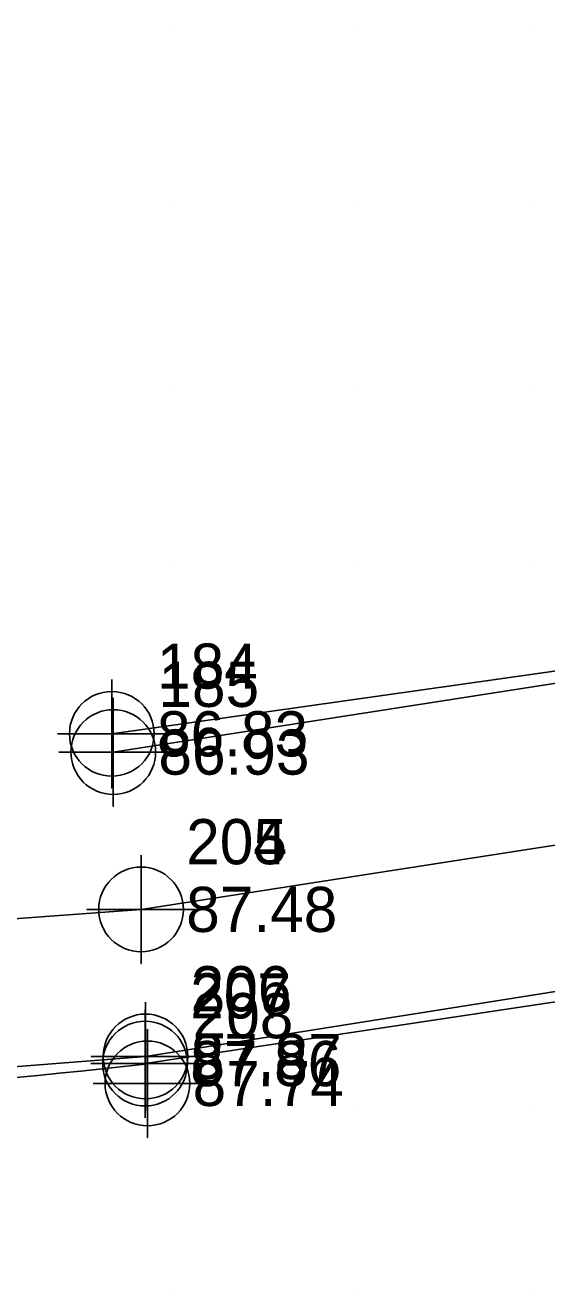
# Model space of a CAD drawing. Extents: x 1988140 to 1988766, y 249950 to 250250.
# Drawn here: x 1988371.8 to 1988400.7, y 250030 to 250100 of the extents above; entities that cross this region are included whole.
import ezdxf

# ---------------------------------------------------------------- set-up
doc = ezdxf.new("R2010")
doc.units = 0
for name, color, linetype in [('Exist DTM Crownline', 7, 'Continuous'), ('Exist DTM Crownline Cogo Elevation', 7, 'Continuous'), ('Exist DTM Crownline Cogo Number', 7, 'Continuous'), ('Exist DTM Crownline Cogo Point CELL', 7, 'Continuous'), ('Exist DTM QL2 LIDAR Elevation Point', 7, 'Continuous'), ('Exist DTM Regular Point CELL', 7, 'Continuous'), ('Exist DTM Regular Point Cogo Elevation', 7, 'Continuous'), ('Exist DTM Regular Point Cogo Number', 7, 'Continuous'), ('Exist Roads EOP', 7, 'Continuous'), ('Exist Roads EOP Cogo Elevation', 7, 'Continuous'), ('Exist Roads EOP Cogo Number', 7, 'Continuous'), ('Exist Roads EOP Cogo Point CELL', 7, 'Continuous'), ('Exist Roads EOT', 7, 'Continuous'), ('Exist Roads EOT Cogo Elevation', 7, 'Continuous'), ('Exist Roads EOT Cogo Number', 7, 'Continuous'), ('Exist Roads EOT Cogo Point CELL', 7, 'Continuous')]:
    doc.layers.add(name, color=color, linetype=linetype)

msp = doc.modelspace()

# ---------------------------------------------------------------- linework, layer by layer
at = {"layer": 'Exist DTM Crownline'}
msp.add_lwpolyline([(1988342.6848, 250048.4444), (1988378.1968, 250051.0543), (1988417.6158, 250057.1729)], dxfattribs=at)
at = {"layer": 'Exist DTM Crownline Cogo Point CELL'}
msp.add_lwpolyline([(1988378.1968, 250054.0543), (1988378.1968, 250048.0543), (1988378.1968, 250051.0543), (1988381.1968, 250051.0543), (1988375.1968, 250051.0543)], dxfattribs=at)
msp.add_circle((1988378.1968, 250051.0543), 2.344, dxfattribs=at)
at = {"layer": 'Exist DTM QL2 LIDAR Elevation Point'}
for p, q in [((1988380, 250100), (1988380, 250100)), ((1988390, 250100), (1988390, 250100)), ((1988400, 250100), (1988400, 250100)), ((1988380, 250090), (1988380, 250090)), ((1988390, 250090), (1988390, 250090)), ((1988400, 250090), (1988400, 250090)), ((1988380, 250080), (1988380, 250080)), ((1988390, 250080), (1988390, 250080)), ((1988400, 250080), (1988400, 250080)), ((1988380, 250070), (1988380, 250070)), ((1988390, 250070), (1988390, 250070)), ((1988400, 250070), (1988400, 250070)), ((1988380, 250040), (1988380, 250040)), ((1988390, 250040), (1988390, 250040)), ((1988400, 250040), (1988400, 250040)), ((1988380, 250030), (1988380, 250030)), ((1988390, 250030), (1988390, 250030)), ((1988400, 250030), (1988400, 250030))]:
    msp.add_line(p, q, dxfattribs=at)
at = {"layer": 'Exist DTM Regular Point CELL'}
msp.add_lwpolyline([(1988378.5524, 250044.4204), (1988378.5524, 250038.4204), (1988378.5524, 250041.4204), (1988381.5524, 250041.4204), (1988375.5524, 250041.4204)], dxfattribs=at)
msp.add_circle((1988378.5524, 250041.4204), 2.344, dxfattribs=at)
at = {"layer": 'Exist Roads EOP'}
for p, q in [((1988376.5794, 250060.7743), (1988415.3306, 250066.2585)), ((1988378.4174, 250042.5183), (1988419.9154, 250048.7733))]:
    msp.add_line(p, q, dxfattribs=at)
msp.add_arc((1988317.1196, 250605.1999), 566.0511, 268.485592, 276.216725, dxfattribs=at)
at = {"layer": 'Exist Roads EOP Cogo Point CELL'}
for points in [[(1988376.5794, 250063.7743), (1988376.5794, 250057.7743), (1988376.5794, 250060.7743), (1988379.5794, 250060.7743), (1988373.5794, 250060.7743)], [(1988378.4174, 250045.5183), (1988378.4174, 250039.5183), (1988378.4174, 250042.5183), (1988381.4174, 250042.5183), (1988375.4174, 250042.5183)]]:
    msp.add_lwpolyline(points, dxfattribs=at)
for centre in [(1988376.5794, 250060.7743), (1988378.4174, 250042.5183)]:
    msp.add_circle(centre, 2.344, dxfattribs=at)
at = {"layer": 'Exist Roads EOT'}
for p, q in [((1988376.6581, 250059.7647), (1988415.3125, 250065.7797)), ((1988342.5427, 250040.1003), (1988378.4449, 250042.9134))]:
    msp.add_line(p, q, dxfattribs=at)
msp.add_lwpolyline([(1988378.4449, 250042.9134), (1988419.6541, 250049.4523)], dxfattribs=at)
at = {"layer": 'Exist Roads EOT Cogo Point CELL'}
for points in [[(1988376.6581, 250062.7647), (1988376.6581, 250056.7647), (1988376.6581, 250059.7647), (1988373.6581, 250059.7647), (1988379.6581, 250059.7647)], [(1988378.1968, 250054.0543), (1988378.1968, 250048.0543), (1988378.1968, 250051.0543), (1988375.1968, 250051.0543), (1988381.1968, 250051.0543)], [(1988378.4449, 250045.9134), (1988378.4449, 250039.9134), (1988378.4449, 250042.9134), (1988375.4449, 250042.9134), (1988381.4449, 250042.9134)]]:
    msp.add_lwpolyline(points, dxfattribs=at)
for centre in [(1988376.6581, 250059.7647), (1988378.1968, 250051.0543), (1988378.4449, 250042.9134)]:
    msp.add_circle(centre, 2.344, dxfattribs=at)

# ---------------------------------------------------------------- texts
at = {"layer": 'Exist DTM Crownline Cogo Elevation'}
msp.add_text('87.48', height=2.5, dxfattribs=at).set_placement((1988380.6968, 250049.8043))
at = {"layer": 'Exist DTM Crownline Cogo Number'}
msp.add_text('204', height=2.5, dxfattribs=at).set_placement((1988380.6968, 250053.5543))
at = {"layer": 'Exist DTM Regular Point Cogo Elevation'}
msp.add_text('87.74', height=2.5, dxfattribs=at).set_placement((1988381.0524, 250040.1704))
at = {"layer": 'Exist DTM Regular Point Cogo Number'}
msp.add_text('208', height=2.5, dxfattribs=at).set_placement((1988381.0524, 250043.9204))
at = {"layer": 'Exist Roads EOP Cogo Elevation'}
for s, p in [('86.83', (1988379.0794, 250059.5243)), ('87.86', (1988380.9174, 250041.2683))]:
    msp.add_text(s, height=2.5, dxfattribs=at).set_placement(p)
at = {"layer": 'Exist Roads EOP Cogo Number'}
for s, p in [('184', (1988379.0794, 250063.2743)), ('207', (1988380.9174, 250045.0183))]:
    msp.add_text(s, height=2.5, dxfattribs=at).set_placement(p)
at = {"layer": 'Exist Roads EOT Cogo Elevation'}
for s, p in [('86.93', (1988379.1581, 250058.5147)), ('87.48', (1988380.6968, 250049.8043)), ('87.87', (1988380.9449, 250041.6634))]:
    msp.add_text(s, height=2.5, dxfattribs=at).set_placement(p)
at = {"layer": 'Exist Roads EOT Cogo Number'}
for s, p in [('185', (1988379.1581, 250062.2647)), ('205', (1988380.6968, 250053.5543)), ('206', (1988380.9449, 250045.4134))]:
    msp.add_text(s, height=2.5, dxfattribs=at).set_placement(p)

doc.saveas('drawing.dxf')
